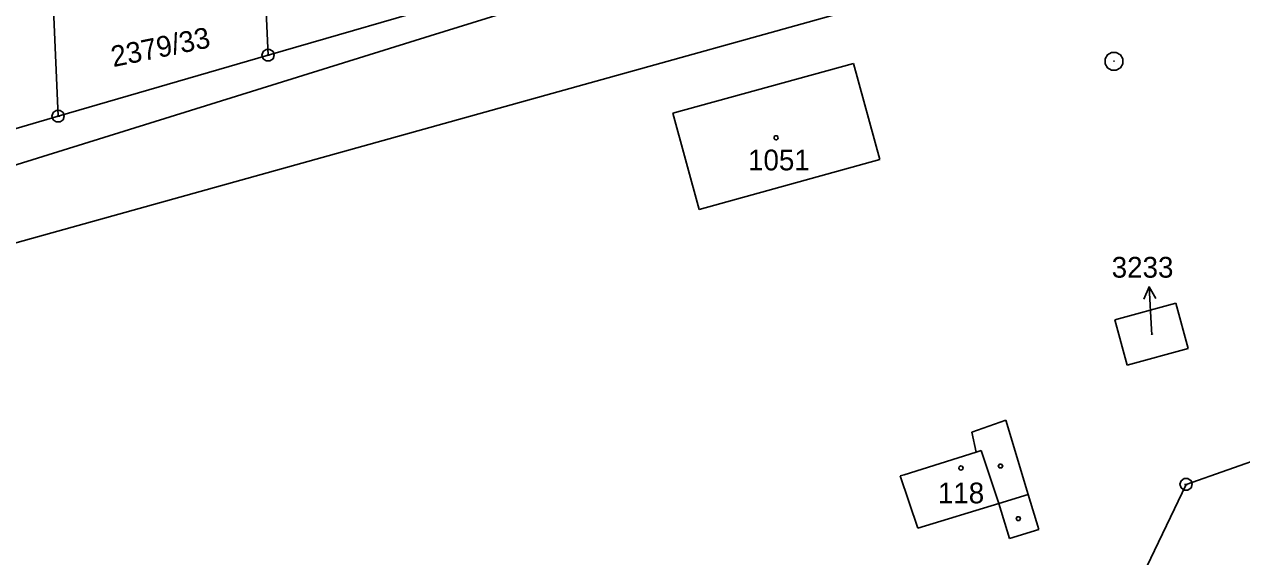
# Model space of a CAD drawing. Extents: x -760611 to -758411, y -1176479 to -1174807.
# Drawn here: x -758724.8 to -758625.1, y -1175037.3 to -1174993.7 of the extents above; entities that cross this region are included whole.
import ezdxf

# ---------------------------------------------------------------- set-up
doc = ezdxf.new("R2010")
doc.units = 0
for name, color, linetype in [('1', 7, 'Continuous'), ('12', 7, 'Continuous'), ('2', 7, 'Continuous'), ('4', 7, 'Continuous'), ('5', 7, 'Continuous'), ('7', 7, 'Continuous'), ('8', 7, 'Continuous')]:
    doc.layers.add(name, color=color, linetype=linetype)

msp = doc.modelspace()

# ---------------------------------------------------------------- linework, layer by layer
at = {"layer": '1'}
for p, q in [((-758598.85, -1174965.89), (-758691.55, -1174994.68)), ((-758704.83, -1174996.27), (-758705.17, -1174988.61)), ((-758648.73, -1174990.25), (-758683.75, -1175000)), ((-758688.59, -1174991.55), (-758704.83, -1174996.27)), ((-758722.03, -1175001.26), (-758722.43, -1174992.51)), ((-758691.55, -1174994.68), (-758772.34, -1175019.78)), ((-758704.83, -1174996.27), (-758722.03, -1175001.26)), ((-758671.67, -1175001), (-758656.88, -1174996.94)), ((-758656.88, -1174996.94), (-758654.72, -1175004.79)), ((-758683.75, -1175000), (-758783.55, -1175027.78)), ((-758722.03, -1175001.26), (-758739.13, -1175006.22)), ((-758669.52, -1175008.88), (-758671.67, -1175001)), ((-758654.72, -1175004.79), (-758669.52, -1175008.88)), ((-758635.46, -1175017.93), (-758630.47, -1175016.57)), ((-758630.47, -1175016.57), (-758629.45, -1175020.28)), ((-758634.44, -1175021.64), (-758635.46, -1175017.93)), ((-758629.45, -1175020.28), (-758634.44, -1175021.64)), ((-758600.05, -1175021.05), (-758629.62, -1175031.39)), ((-758647.17, -1175027.11), (-758644.4, -1175026.13)), ((-758644.4, -1175026.13), (-758642.56, -1175032.21)), ((-758646.82, -1175028.75), (-758647.17, -1175027.11)), ((-758652.71, -1175030.6), (-758646.82, -1175028.75)), ((-758653.04, -1175030.7), (-758652.71, -1175030.6)), ((-758651.6, -1175034.96), (-758653.04, -1175030.7)), ((-758629.62, -1175031.39), (-758633.16, -1175038.79)), ((-758642.56, -1175032.21), (-758641.69, -1175035.08)), ((-758644.97, -1175032.94), (-758651.6, -1175034.96)), ((-758644.1, -1175035.81), (-758644.97, -1175032.94)), ((-758641.69, -1175035.08), (-758644.1, -1175035.81))]:
    msp.add_line(p, q, dxfattribs=at)
at = {"layer": '12'}
for p, q in [((-758671.67, -1175001), (-758656.88, -1174996.94)), ((-758656.88, -1174996.94), (-758654.72, -1175004.79)), ((-758669.52, -1175008.88), (-758671.67, -1175001)), ((-758654.72, -1175004.79), (-758669.52, -1175008.88)), ((-758652.71, -1175030.6), (-758646.82, -1175028.75)), ((-758646.82, -1175028.75), (-758646.41, -1175028.62)), ((-758646.41, -1175028.62), (-758644.97, -1175032.94)), ((-758653.04, -1175030.7), (-758652.71, -1175030.6)), ((-758651.6, -1175034.96), (-758653.04, -1175030.7)), ((-758644.97, -1175032.94), (-758651.6, -1175034.96))]:
    msp.add_line(p, q, dxfattribs=at)
at = {"layer": '4'}
for p, q in [((-758646.82, -1175028.75), (-758646.41, -1175028.62)), ((-758646.41, -1175028.62), (-758644.97, -1175032.94)), ((-758644.97, -1175032.94), (-758642.56, -1175032.21))]:
    msp.add_line(p, q, dxfattribs=at)
at = {"layer": '5'}
for points in [[(-758663.21, -1175002.85), (-758663.11, -1175002.87), (-758663.06, -1175002.96), (-758663.04, -1175003.02), (-758663.06, -1175003.11), (-758663.14, -1175003.18), (-758663.21, -1175003.19), (-758663.3, -1175003.16), (-758663.36, -1175003.1), (-758663.38, -1175003.02), (-758663.36, -1175002.93), (-758663.28, -1175002.86)], [(-758648.07, -1175029.88), (-758647.97, -1175029.9), (-758647.92, -1175029.99), (-758647.9, -1175030.05), (-758647.92, -1175030.14), (-758648, -1175030.21), (-758648.07, -1175030.22), (-758648.16, -1175030.19), (-758648.22, -1175030.13), (-758648.24, -1175030.05), (-758648.22, -1175029.96), (-758648.14, -1175029.89)], [(-758644.74, -1175029.74), (-758644.65, -1175029.89), (-758644.74, -1175030.04), (-758644.92, -1175030.04), (-758645.01, -1175029.89), (-758644.92, -1175029.74)], [(-758643.28, -1175034.03), (-758643.19, -1175034.18), (-758643.28, -1175034.33), (-758643.46, -1175034.33), (-758643.55, -1175034.18), (-758643.46, -1175034.03)]]:
    msp.add_lwpolyline(points, close=True, dxfattribs=at)
at = {"layer": '7'}
for p in [(-758632.652, -1175015.214), (-758632.44, -1175019.14)]:
    msp.add_line(p, (-758632.49, -1175018.21), dxfattribs=at)
msp.add_lwpolyline([(-758633.097, -1175016.24), (-758632.652, -1175015.214), (-758632.099, -1175016.186)], dxfattribs=at)
at = {"layer": '8'}
for p, q in [((-758704.95, -1174996.27), (-758704.71, -1174996.27)), ((-758635.58, -1174996.76), (-758635.48, -1174996.76)), ((-758722.15, -1175001.26), (-758721.91, -1175001.26)), ((-758629.74, -1175031.39), (-758629.5, -1175031.39))]:
    msp.add_line(p, q, dxfattribs=at)
for points in [[(-758704.68, -1174995.79), (-758704.43, -1174995.97), (-758704.33, -1174996.26), (-758704.43, -1174996.55), (-758704.68, -1174996.73), (-758704.99, -1174996.73), (-758705.24, -1174996.55), (-758705.34, -1174996.26), (-758705.24, -1174995.97), (-758704.99, -1174995.79)], [(-758635.34, -1174996.04), (-758635, -1174996.23), (-758634.81, -1174996.57), (-758634.81, -1174996.96), (-758635, -1174997.3), (-758635.34, -1174997.49), (-758635.73, -1174997.49), (-758636.07, -1174997.3), (-758636.26, -1174996.96), (-758636.26, -1174996.57), (-758636.07, -1174996.23), (-758635.73, -1174996.04)], [(-758721.88, -1175000.78), (-758721.63, -1175000.96), (-758721.53, -1175001.25), (-758721.63, -1175001.54), (-758721.88, -1175001.72), (-758722.19, -1175001.72), (-758722.44, -1175001.54), (-758722.54, -1175001.25), (-758722.44, -1175000.96), (-758722.19, -1175000.78)], [(-758629.47, -1175030.91), (-758629.22, -1175031.09), (-758629.12, -1175031.38), (-758629.22, -1175031.67), (-758629.47, -1175031.85), (-758629.78, -1175031.85), (-758630.03, -1175031.67), (-758630.13, -1175031.38), (-758630.03, -1175031.09), (-758629.78, -1175030.91)]]:
    msp.add_lwpolyline(points, close=True, dxfattribs=at)

# ---------------------------------------------------------------- texts
at = {"layer": '2'}
msp.add_text('2379/33', height=1.7, rotation=11.51645, dxfattribs=at).set_placement((-758717.517, -1174997.243))
for s, height, p in [('1051', 1.7, (-758665.511, -1175005.69)), ('3233', 0.1, (-758632.615, -1175019.14)), ('118', 1.7, (-758649.958, -1175032.94))]:
    msp.add_text(s, height=height, dxfattribs=at).set_placement(p)
at = {"layer": '7'}
msp.add_text('3233', height=1.7, dxfattribs=at).set_placement((-758635.718, -1175014.47))

doc.saveas('drawing.dxf')
